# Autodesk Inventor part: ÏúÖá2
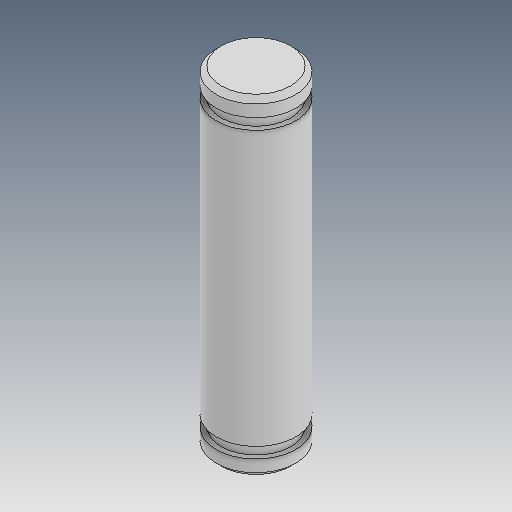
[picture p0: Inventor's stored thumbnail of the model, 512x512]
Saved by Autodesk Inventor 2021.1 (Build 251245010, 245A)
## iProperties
Created: 2013-04
Part Number: ÏúÖá2
Material: Ogólny
Document SubType Name: Modeling
Designer: user
Density: 1 g/cm^3
Appearance: Domyślna
Author: user
Revision Number: ÈÎºÎ
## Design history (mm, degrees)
feature "Ðý×ª1"
node "Bryła1"
